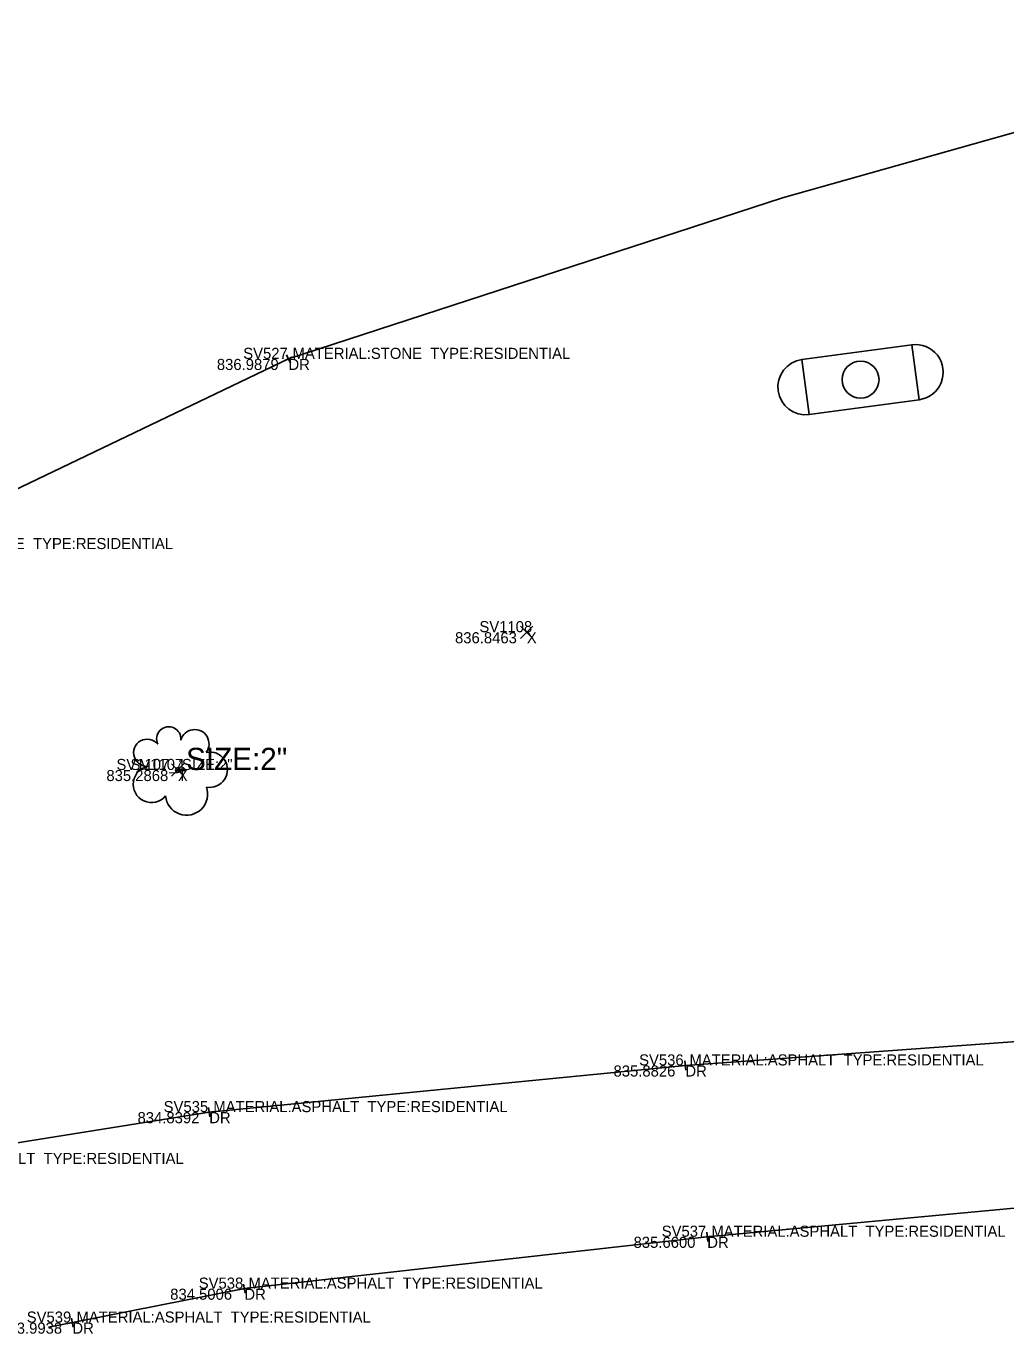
# Model space of a CAD drawing. Extents: x 1715717 to 1717046, y 393954 to 396000.
# Drawn here: x 1716230.5 to 1716283.5, y 394803.1 to 394873.9 of the extents above; entities that cross this region are included whole.
import ezdxf

# ---------------------------------------------------------------- set-up
doc = ezdxf.new("R2010")
doc.units = 0
for name, color, linetype in [('PV_X_Driveway', 7, 'Continuous'), ('SV_X_Random_Point', 7, 'Continuous'), ('SV_X_Shot_Marker', 7, 'Continuous'), ('SV_X_Text_Comment', 7, 'Continuous'), ('SV_X_Text_Description', 7, 'Continuous'), ('SV_X_Text_Elevation', 7, 'Continuous'), ('SV_X_Text_Name', 7, 'Continuous'), ('UT_X_Tank', 7, 'Continuous'), ('VG_X_Cells', 7, 'Continuous'), ('VG_X_Text', 7, 'Continuous')]:
    doc.layers.add(name, color=color, linetype=linetype)

msp = doc.modelspace()

# ---------------------------------------------------------------- linework, layer by layer
at = {"layer": 'PV_X_Driveway'}
for p, q in [((1716271.447, 394864.578), (1716304.324, 394873.869)), ((1716244.721, 394855.862), (1716271.447, 394864.578)), ((1716266.196, 394817.626), (1716361.881, 394824.579)), ((1716267.38, 394808.355), (1716359.809, 394817.012)), ((1716267.38, 394808.355), (1716242.338, 394805.547)), ((1716242.338, 394805.547), (1716233.032, 394803.71)), ((1716233.032, 394803.71), (1716231.738, 394803.454))]:
    msp.add_line(p, q, dxfattribs=at)
for points in [[(1716244.721, 394855.862), (1716223.232, 394845.571), (1716209.609, 394831.096), (1716202.101, 394818.322)], [(1716203.927, 394814.333), (1716222.914, 394812.297), (1716240.435, 394815.099), (1716266.196, 394817.626)]]:
    msp.add_lwpolyline(points, dxfattribs=at)
at = {"layer": 'SV_X_Random_Point'}
for p, q in [((1716257.283, 394840.738), (1716257.95, 394841.405)), ((1716257.283, 394841.405), (1716257.95, 394840.738)), ((1716238.402, 394833.281), (1716239.069, 394833.949)), ((1716238.402, 394833.949), (1716239.069, 394833.281))]:
    msp.add_line(p, q, dxfattribs=at)
at = {"layer": 'SV_X_Shot_Marker'}
for p, q in [((1716244.946, 394855.97), (1716244.495, 394855.754)), ((1716244.829, 394855.636), (1716244.613, 394856.087)), ((1716244.721, 394855.862), (1716244.721, 394855.862)), ((1716265.948, 394817.601), (1716266.445, 394817.65)), ((1716266.172, 394817.875), (1716266.221, 394817.377)), ((1716266.196, 394817.626), (1716266.196, 394817.626)), ((1716240.395, 394815.346), (1716240.474, 394814.852)), ((1716240.188, 394815.06), (1716240.682, 394815.139)), ((1716240.435, 394815.099), (1716240.435, 394815.099)), ((1716267.628, 394808.383), (1716267.132, 394808.328)), ((1716267.408, 394808.107), (1716267.352, 394808.604)), ((1716267.38, 394808.355), (1716267.38, 394808.355)), ((1716242.584, 394805.595), (1716242.093, 394805.498)), ((1716242.387, 394805.302), (1716242.29, 394805.792)), ((1716242.338, 394805.547), (1716242.338, 394805.547)), ((1716233.08, 394803.465), (1716232.983, 394803.955)), ((1716233.277, 394803.758), (1716232.786, 394803.661)), ((1716233.032, 394803.71), (1716233.032, 394803.71))]:
    msp.add_line(p, q, dxfattribs=at)
at = {"layer": 'UT_X_Tank'}
for p, q in [((1716272.498, 394855.823), (1716278.444, 394856.628)), ((1716278.846, 394853.655), (1716278.444, 394856.628)), ((1716272.9, 394852.85), (1716272.498, 394855.823)), ((1716272.9, 394852.85), (1716278.846, 394853.655))]:
    msp.add_line(p, q, dxfattribs=at)
msp.add_circle((1716275.672, 394854.739), 1, dxfattribs=at)
for centre, start, end in [((1716278.645, 394855.142), 277.70926, 97.70926), ((1716272.699, 394854.337), 97.70926, 277.70926)]:
    msp.add_arc(centre, 1.5, start, end, dxfattribs=at)
at = {"layer": 'VG_X_Cells'}
msp.add_circle((1716238.736, 394833.615), 0.12, dxfattribs=at)
for centre, radius, start, end in [((1716238.244, 394835.299), 0.658, 354.0047, 205.97412), ((1716239.649, 394835.029), 0.776, 323.82996, 165.0376), ((1716237.081, 394834.547), 0.735, 39.06254, 279.54124), ((1716240.466, 394833.633), 0.957, 259.14531, 101.45961), ((1716237.309, 394832.841), 0.987, 96.17219, 320.57371), ((1716239.209, 394832.312), 1.142, 184.94757, 19.45715)]:
    msp.add_arc(centre, radius, start, end, dxfattribs=at)

# ---------------------------------------------------------------- texts
at = {"layer": 'SV_X_Text_Comment'}
for s, p in [('DR', (1716244.721, 394855.262)), ('X', (1716257.616, 394840.472)), ('T', (1716238.736, 394833.015)), ('X', (1716238.736, 394833.015)), ('DR', (1716266.196, 394817.026)), ('DR', (1716240.435, 394814.499)), ('DR', (1716267.38, 394807.755)), ('DR', (1716242.338, 394804.947)), ('DR', (1716233.032, 394803.11))]:
    msp.add_text(s, height=0.6, dxfattribs=at).set_placement(p)
at = {"layer": 'SV_X_Text_Description'}
for s, p in [(' MATERIAL:STONE  TYPE:RESIDENTIAL ', (1716244.721, 394855.862)), (' MATERIAL:STONE  TYPE:RESIDENTIAL ', (1716223.232, 394845.571)), (' SIZE:2" ', (1716238.736, 394833.615)), (' MATERIAL:ASPHALT  TYPE:RESIDENTIAL ', (1716266.196, 394817.626)), (' MATERIAL:ASPHALT  TYPE:RESIDENTIAL ', (1716240.435, 394815.099)), (' MATERIAL:ASPHALT  TYPE:RESIDENTIAL ', (1716222.914, 394812.297)), (' MATERIAL:ASPHALT  TYPE:RESIDENTIAL ', (1716267.38, 394808.355)), (' MATERIAL:ASPHALT  TYPE:RESIDENTIAL ', (1716242.338, 394805.547)), (' MATERIAL:ASPHALT  TYPE:RESIDENTIAL ', (1716233.032, 394803.71))]:
    msp.add_text(s, height=0.6, dxfattribs=at).set_placement(p)
at = {"layer": 'SV_X_Text_Elevation'}
for s, p in [('836.9879', (1716240.847, 394855.262)), ('836.8463', (1716253.733, 394840.472)), ('835.2868', (1716234.871, 394833.015)), ('835.2868', (1716234.871, 394833.015)), ('835.8826', (1716262.308, 394817.026)), ('834.8392', (1716236.556, 394814.499)), ('835.6600', (1716263.393, 394807.755)), ('834.5006', (1716238.323, 394804.947)), ('833.9938', (1716229.129, 394803.11))]:
    msp.add_text(s, height=0.6, dxfattribs=at).set_placement(p)
at = {"layer": 'SV_X_Text_Name'}
for s, p in [('SV527', (1716242.274, 394855.862)), ('SV1108', (1716255.052, 394841.072)), ('SV1107_1', (1716235.415, 394833.615)), ('SV1107', (1716236.176, 394833.615)), ('SV536', (1716263.693, 394817.626)), ('SV535', (1716237.969, 394815.099)), ('SV537', (1716264.914, 394808.355)), ('SV538', (1716239.868, 394805.547)), ('SV539', (1716230.561, 394803.71))]:
    msp.add_text(s, height=0.6, dxfattribs=at).set_placement(p)
at = {"layer": 'VG_X_Text'}
msp.add_text(' SIZE:2" ', height=1.2, dxfattribs=at).set_placement((1716238.736, 394833.615))

doc.saveas('drawing.dxf')
